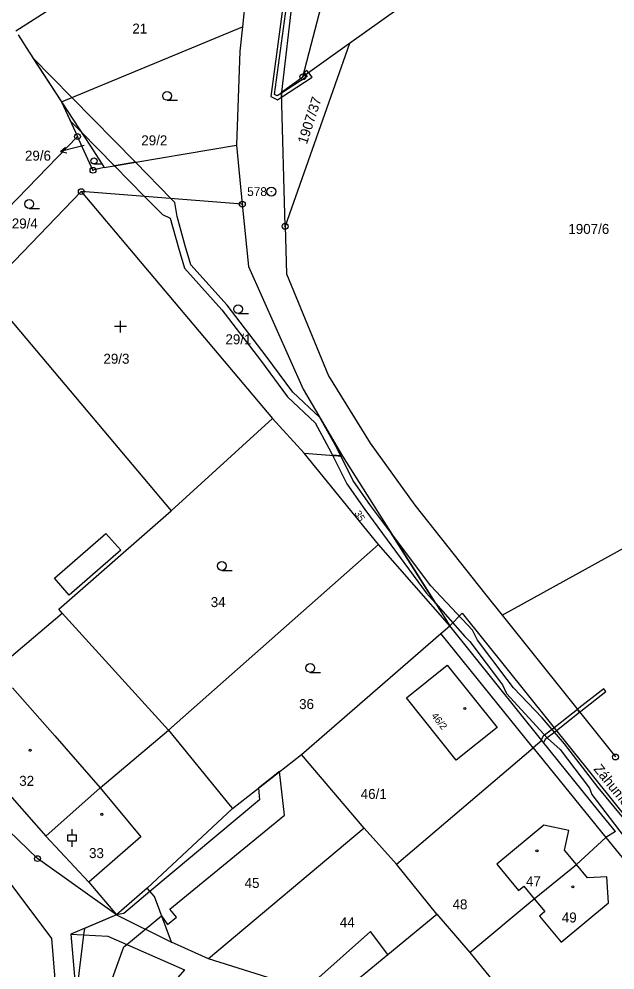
# Model space of a CAD drawing. Extents: x -504988 to -494607, y -1123820 to -1114018.
# Drawn here: x -497661.1 to -497559.8, y -1119332.3 to -1119170.5 of the extents above; entities that cross this region are included whole.
import ezdxf

# ---------------------------------------------------------------- set-up
doc = ezdxf.new("R2010")
doc.units = 0
for name, color, linetype in [('Hranice parcel', 7, 'Continuous'), ('Parcelní čísla', 7, 'Continuous'), ('Pop  PČ popisy', 7, 'Continuous'), ('Vnitřní kresba', 7, 'Continuous'), ('Věcná břemena k části', 7, 'Continuous'), ('Značky bodu BP', 7, 'Continuous'), ('Značky budov', 7, 'Continuous'), ('Značky kultur', 7, 'Continuous')]:
    doc.layers.add(name, color=color, linetype=linetype)

msp = doc.modelspace()

# ---------------------------------------------------------------- linework, layer by layer
at = {"layer": 'Hranice parcel'}
for p, q in [((-497561.55, -1119143.66), (-497604.89, -1119174.64)), ((-497661.69, -1119172.47), (-497620.57, -1119146.31)), ((-497620.57, -1119146.31), (-497623.13, -1119171.83)), ((-497612.83, -1119180.31), (-497605.5, -1119151.88)), ((-497613.56, -1119157.81), (-497616.5, -1119182.92)), ((-497653.87, -1119184.57), (-497623.13, -1119171.83)), ((-497604.89, -1119174.64), (-497615.86, -1119205.74)), ((-497604.89, -1119174.64), (-497612.83, -1119180.31)), ((-497616.5, -1119182.92), (-497612.83, -1119180.31)), ((-497615.86, -1119205.74), (-497616.5, -1119182.92)), ((-497653.87, -1119184.57), (-497651.17, -1119190.47)), ((-497651.17, -1119190.47), (-497672.74, -1119212.67)), ((-497624.14, -1119191.91), (-497623.14, -1119201.99)), ((-497650.53, -1119199.84), (-497666.81, -1119216.69)), ((-497623.14, -1119201.99), (-497650.53, -1119199.84)), ((-497650.53, -1119199.84), (-497618.02, -1119238.44)), ((-497666.81, -1119216.69), (-497635.22, -1119254.15)), ((-497635.22, -1119254.15), (-497618.02, -1119238.44)), ((-497618.02, -1119238.44), (-497612.63, -1119244.34)), ((-497612.63, -1119244.34), (-497606.1, -1119244.83)), ((-497599.98, -1119259.89), (-497612.63, -1119244.34)), ((-497606.1, -1119244.83), (-497587.86, -1119273.73)), ((-497578.93, -1119271.92), (-497547.89, -1119254.72)), ((-497599.98, -1119259.89), (-497635.7, -1119291.45)), ((-497587.86, -1119273.73), (-497599.98, -1119259.89)), ((-497635.7, -1119291.45), (-497653.77, -1119271.55)), ((-497578.93, -1119271.92), (-497559.68, -1119296.02)), ((-497589.37, -1119275.03), (-497587.86, -1119273.73)), ((-497613.09, -1119295.59), (-497589.37, -1119275.03)), ((-497573.66, -1119294.45), (-497589.37, -1119275.03)), ((-497596.89, -1119314.28), (-497573.66, -1119294.45)), ((-497573.66, -1119294.45), (-497561.3, -1119309.73)), ((-497624.81, -1119304.8), (-497613.09, -1119295.59)), ((-497602.42, -1119308.13), (-497613.09, -1119295.59)), ((-497624.81, -1119304.8), (-497639.34, -1119318.35)), ((-497602.42, -1119308.13), (-497628.88, -1119330.34)), ((-497596.89, -1119314.28), (-497602.42, -1119308.13)), ((-497566.3, -1119314.29), (-497561.3, -1119309.73)), ((-497561.3, -1119309.73), (-497549.05, -1119324.87)), ((-497644.56, -1119322.87), (-497657.98, -1119313.31)), ((-497590.06, -1119322.78), (-497596.89, -1119314.28)), ((-497573.48, -1119320.16), (-497566.3, -1119314.29)), ((-497639.34, -1119318.35), (-497644.56, -1119322.87)), ((-497584.44, -1119329.26), (-497573.48, -1119320.16)), ((-497644.56, -1119322.87), (-497652.3, -1119326.14)), ((-497598.41, -1119329.63), (-497590.06, -1119322.78)), ((-497590.06, -1119322.78), (-497584.44, -1119329.26)), ((-497652.3, -1119326.14), (-497650.03, -1119351.83)), ((-497584.44, -1119329.26), (-497572.13, -1119344.3)), ((-497618.71, -1119346.31), (-497598.41, -1119329.63))]:
    msp.add_line(p, q, dxfattribs=at)
for points in [[(-497623.13, -1119171.83), (-497623.54, -1119175.96), (-497624.14, -1119191.91)], [(-497661.25, -1119173.18), (-497659.42, -1119176.11), (-497653.87, -1119184.57)], [(-497653.87, -1119184.57), (-497648.98, -1119192.12), (-497646.63, -1119195.76)], [(-497646.63, -1119195.76), (-497648.54, -1119196.21), (-497651.17, -1119190.47)], [(-497646.63, -1119195.76), (-497645.63, -1119195.59), (-497624.14, -1119191.91)], [(-497623.14, -1119201.99), (-497622.09, -1119212.58), (-497612.77, -1119233.43), (-497606.1, -1119244.83)], [(-497615.86, -1119205.74), (-497615.64, -1119213.8), (-497608.48, -1119231.19), (-497601.38, -1119242.66), (-497593.78, -1119253.19), (-497581.74, -1119268.41), (-497578.93, -1119271.92)], [(-497653.77, -1119271.55), (-497654.37, -1119270.88), (-497635.22, -1119254.15)], [(-497675.97, -1119286.71), (-497670.32, -1119284.67), (-497666.59, -1119282.37), (-497653.77, -1119271.55)], [(-497586.77, -1119296.57), (-497595.23, -1119285.95), (-497588.27, -1119280.41), (-497579.81, -1119291.03), (-497586.77, -1119296.57)], [(-497675.97, -1119286.71), (-497671.2, -1119292.26), (-497664.15, -1119300.47), (-497664.32, -1119300.62), (-497656.56, -1119309.48)], [(-497657.98, -1119313.31), (-497672.67, -1119299.18), (-497679.68, -1119290.51)], [(-497656.56, -1119309.48), (-497647.32, -1119301.25), (-497635.7, -1119291.45)], [(-497635.7, -1119291.45), (-497625.18, -1119304.33), (-497624.81, -1119304.8)], [(-497566.3, -1119314.29), (-497568.32, -1119311.86), (-497567.61, -1119308.51), (-497571.84, -1119307.62), (-497579.87, -1119314.28), (-497576.16, -1119318.75), (-497575.26, -1119318), (-497573.48, -1119320.16)], [(-497656.56, -1119309.48), (-497649.25, -1119317.34), (-497644.56, -1119322.87)], [(-497653.7, -1119349.05), (-497655.52, -1119326.88), (-497664.73, -1119314.68)], [(-497573.48, -1119320.16), (-497571.67, -1119322.33), (-497572.6, -1119323.1), (-497568.92, -1119327.53), (-497560.87, -1119320.83), (-497561.11, -1119316.39), (-497564.41, -1119316.57), (-497566.3, -1119314.29)], [(-497628.88, -1119330.34), (-497635.2, -1119327.53), (-497638.1, -1119319.77), (-497639.34, -1119318.35)], [(-497652.3, -1119326.14), (-497646.02, -1119326.5), (-497632.98, -1119332.21), (-497650.03, -1119351.83)], [(-497598.41, -1119329.63), (-497601.36, -1119325.72), (-497611.16, -1119334.43), (-497616.84, -1119334.17), (-497628.88, -1119330.34)]]:
    msp.add_lwpolyline(points, dxfattribs=at)
at = {"layer": 'Pop  PČ popisy'}
for p, q in [((-497651.16, -1119192.27), (-497654.07, -1119193)), ((-497654.07, -1119193), (-497653.22, -1119192.27)), ((-497654.07, -1119193), (-497652.98, -1119193.24)), ((-497650.05, -1119192.01), (-497651.16, -1119192.27))]:
    msp.add_line(p, q, dxfattribs=at)
at = {"layer": 'Vnitřní kresba'}
for p, q in [((-497655.08, -1119265.61), (-497646.34, -1119258.01)), ((-497646.34, -1119258.01), (-497643.83, -1119260.85)), ((-497643.83, -1119260.85), (-497652.57, -1119268.5)), ((-497652.57, -1119268.5), (-497655.08, -1119265.61)), ((-497587.86, -1119273.73), (-497585.74, -1119271.57)), ((-497585.74, -1119271.57), (-497545.39, -1119321.91)), ((-497572.18, -1119293.2), (-497587.86, -1119273.73)), ((-497662.21, -1119284.26), (-497655.04, -1119292.44)), ((-497655.04, -1119292.44), (-497647.32, -1119301.25)), ((-497572.18, -1119293.2), (-497573.66, -1119294.45)), ((-497562.5, -1119305.22), (-497572.18, -1119293.2)), ((-497647.32, -1119301.25), (-497640.4, -1119309.63)), ((-497559.66, -1119308.7), (-497562.5, -1119305.22)), ((-497640.4, -1119309.63), (-497649.25, -1119317.34)), ((-497559.66, -1119308.7), (-497561.3, -1119309.73)), ((-497644.56, -1119322.87), (-497635.2, -1119327.53))]:
    msp.add_line(p, q, dxfattribs=at)
at = {"layer": 'Věcná břemena k části'}
for points in [[(-497618.31, -1119183.68), (-497617.15, -1119184.23), (-497616.48, -1119183.79), (-497616.5, -1119183.1), (-497617.19, -1119183.55), (-497617.65, -1119183.32), (-497614.45, -1119159.54), (-497615.99, -1119158.55), (-497616.08, -1119146.98), (-497614.56, -1119145.89), (-497614.68, -1119139.36), (-497614.28, -1119138.6), (-497615.7, -1119137.49), (-497615.41, -1119129.81), (-497613.91, -1119128.68), (-497616, -1119129.76), (-497616.32, -1119137.77), (-497615.04, -1119138.76), (-497615.28, -1119139.22), (-497615.16, -1119145.59), (-497616.68, -1119146.68), (-497616.59, -1119158.89), (-497615.09, -1119159.84)], [(-497652.12, -1119183.85), (-497658.81, -1119177.03), (-497653.87, -1119184.57), (-497652.38, -1119187.83), (-497650.56, -1119189.69), (-497644.88, -1119195.46), (-497641.32, -1119194.85)], [(-497616.5, -1119183.1), (-497616.48, -1119183.79), (-497611.23, -1119180.38), (-497611.85, -1119179.61), (-497612.18, -1119179.21), (-497612.64, -1119179.58), (-497612.34, -1119179.96), (-497612.11, -1119180.24)], [(-497641.32, -1119194.85), (-497644.88, -1119195.46), (-497639.76, -1119200.69), (-497636.74, -1119203.76), (-497635.4, -1119204.37), (-497634.01, -1119209.4), (-497632.97, -1119212.88), (-497626.64, -1119219.93), (-497620.06, -1119228.54), (-497615.43, -1119234.73), (-497610.74, -1119239.16), (-497608.41, -1119243.46), (-497607.79, -1119244.7), (-497606.4, -1119244.81), (-497607.35, -1119242.9), (-497609.94, -1119238.27), (-497614.53, -1119233.93), (-497619.1, -1119227.82), (-497625.72, -1119219.17), (-497631.89, -1119212.28), (-497632.85, -1119209.06), (-497634.24, -1119204.05), (-497634.6, -1119201.69), (-497635.24, -1119201.04)], [(-497602.32, -1119253.93), (-497591.89, -1119268.08), (-497590.29, -1119269.88), (-497597.92, -1119257.79), (-497601.34, -1119253.23), (-497604.34, -1119248.93), (-497606.4, -1119244.81), (-497607.79, -1119244.7), (-497605.38, -1119249.55)], [(-497565.77, -1119288.39), (-497565.56, -1119288.22), (-497561.3, -1119284.9), (-497561.66, -1119284.42), (-497562.12, -1119284.75), (-497565.89, -1119287.73), (-497566.15, -1119287.93)], [(-497566.15, -1119287.93), (-497570.38, -1119291.27), (-497571.96, -1119292.5), (-497572.36, -1119293.22), (-497571.84, -1119293.52), (-497571.49, -1119292.9), (-497570.01, -1119291.75), (-497565.77, -1119288.39)], [(-497616.8, -1119298.5), (-497620.41, -1119301.35), (-497620.19, -1119303.31), (-497638.85, -1119318.91), (-497643.29, -1119322.62), (-497644.56, -1119322.87), (-497650, -1119325.17), (-497650.13, -1119326.26), (-497651.38, -1119336.54), (-497650.37, -1119347.95), (-497643.29, -1119328.33), (-497642.79, -1119327.91), (-497636.87, -1119323.06), (-497635.89, -1119324.54), (-497634.34, -1119323.27), (-497635.47, -1119321.91), (-497615.95, -1119305.9)]]:
    msp.add_lwpolyline(points, close=True, dxfattribs=at)
msp.add_lwpolyline([(-497555.83, -1119309.43), (-497562.64, -1119301.22), (-497568.34, -1119293.76), (-497572.15, -1119289.36), (-497577.04, -1119284.23), (-497578.07, -1119282.86), (-497583.12, -1119276.16), (-497583.96, -1119274.46), (-497591.08, -1119266.91), (-497597.92, -1119257.79), (-497590.29, -1119269.88), (-497585.28, -1119275.52), (-497584.44, -1119276.4), (-497578.9, -1119283.76), (-497578.19, -1119285.22), (-497571.25, -1119292.82), (-497569.09, -1119294.75), (-497564.07, -1119301.33), (-497563.71, -1119302.43), (-497558.17, -1119309.58)], dxfattribs=at)
at = {"layer": 'Značky bodu BP'}
for centre, radius in [((-497612.83, -1119180.31), 0.5), ((-497612.83, -1119180.31), 0.0303), ((-497651.17, -1119190.47), 0.5), ((-497651.17, -1119190.47), 0.0303), ((-497648.54, -1119196.21), 0.5), ((-497648.54, -1119196.21), 0.0303), ((-497650.53, -1119199.84), 0.5), ((-497650.53, -1119199.84), 0.0303), ((-497618.21, -1119199.84), 0.75), ((-497618.21, -1119199.84), 0.03), ((-497623.14, -1119201.99), 0.5), ((-497623.14, -1119201.99), 0.0303), ((-497615.86, -1119205.74), 0.5), ((-497615.86, -1119205.74), 0.0303), ((-497559.68, -1119296.02), 0.5), ((-497657.98, -1119313.31), 0.5), ((-497657.98, -1119313.31), 0.0303)]:
    msp.add_circle(centre, radius, dxfattribs=at)
at = {"layer": 'Značky budov'}
for centre in [(-497585.3, -1119287.77), (-497659.21, -1119294.88), (-497647.04, -1119305.78), (-497573.02, -1119311.98), (-497566.92, -1119318.12)]:
    msp.add_circle(centre, 0.175, dxfattribs=at)
at = {"layer": 'Značky kultur'}
for p, q in [((-497635.93, -1119184.31), (-497634.18, -1119184.31)), ((-497648.36, -1119195.14), (-497647.13, -1119195.14)), ((-497659.38, -1119202.69), (-497657.63, -1119202.69)), ((-497623.86, -1119220.58), (-497622.11, -1119220.58)), ((-497643.86, -1119223.8), (-497643.86, -1119221.8)), ((-497642.86, -1119222.8), (-497644.86, -1119222.8)), ((-497626.62, -1119264.27), (-497624.87, -1119264.27)), ((-497611.59, -1119281.62), (-497609.84, -1119281.62)), ((-497652.07, -1119309.28), (-497652.07, -1119308.28)), ((-497652.82, -1119309.28), (-497651.32, -1119309.28)), ((-497652.82, -1119310.28), (-497652.82, -1119309.28)), ((-497651.32, -1119310.28), (-497651.32, -1119309.28)), ((-497652.82, -1119310.28), (-497651.32, -1119310.28)), ((-497652.07, -1119311.28), (-497652.07, -1119310.28))]:
    msp.add_line(p, q, dxfattribs=at)
for centre, radius in [((-497635.93, -1119183.56), 0.75), ((-497648.36, -1119194.61), 0.525), ((-497659.38, -1119201.94), 0.75), ((-497623.86, -1119219.83), 0.75), ((-497626.62, -1119263.52), 0.75), ((-497611.59, -1119280.87), 0.75)]:
    msp.add_circle(centre, radius, dxfattribs=at)

# ---------------------------------------------------------------- texts
at = {"layer": 'Parcelní čísla'}
for s, p in [('21', (-497641.84, -1119172.95)), ('29/2', (-497640.32, -1119191.97)), ('29/6', (-497660.11, -1119194.57)), ('29/4', (-497662.35, -1119206.11)), ('1907/6', (-497567.68, -1119207.04)), ('29/1', (-497626.01, -1119225.81)), ('29/3', (-497646.76, -1119229.12)), ('34', (-497628.51, -1119270.52)), ('36', (-497613.48, -1119287.87)), ('32', (-497661.08, -1119300.93)), ('46/1', (-497603, -1119303.16)), ('33', (-497649.21, -1119313.22)), ('47', (-497574.89, -1119318.03)), ('45', (-497622.75, -1119318.31)), ('48', (-497587.38, -1119321.94)), ('49', (-497568.79, -1119324.17)), ('44', (-497606.55, -1119324.99))]:
    msp.add_text(s, height=1.7, dxfattribs=at).set_placement(p)
for s, height, rotation, p in [('1907/37', 1.7, 72, (-497612.17, -1119191.88)), ('35', 1.2, 302, (-497604.14, -1119254.56)), ('46/2', 1.2, 308, (-497591.06, -1119289.04))]:
    msp.add_text(s, height=height, rotation=rotation, dxfattribs=at).set_placement(p)
at = {"layer": 'Pop  PČ popisy'}
msp.add_text('Záhumení', height=1.7, rotation=309, dxfattribs=at).set_placement((-497563.49, -1119298.1))
at = {"layer": 'Značky bodu BP'}
msp.add_text('578', height=1.5, dxfattribs=at).set_placement((-497622.31, -1119200.59))

doc.saveas('drawing.dxf')
